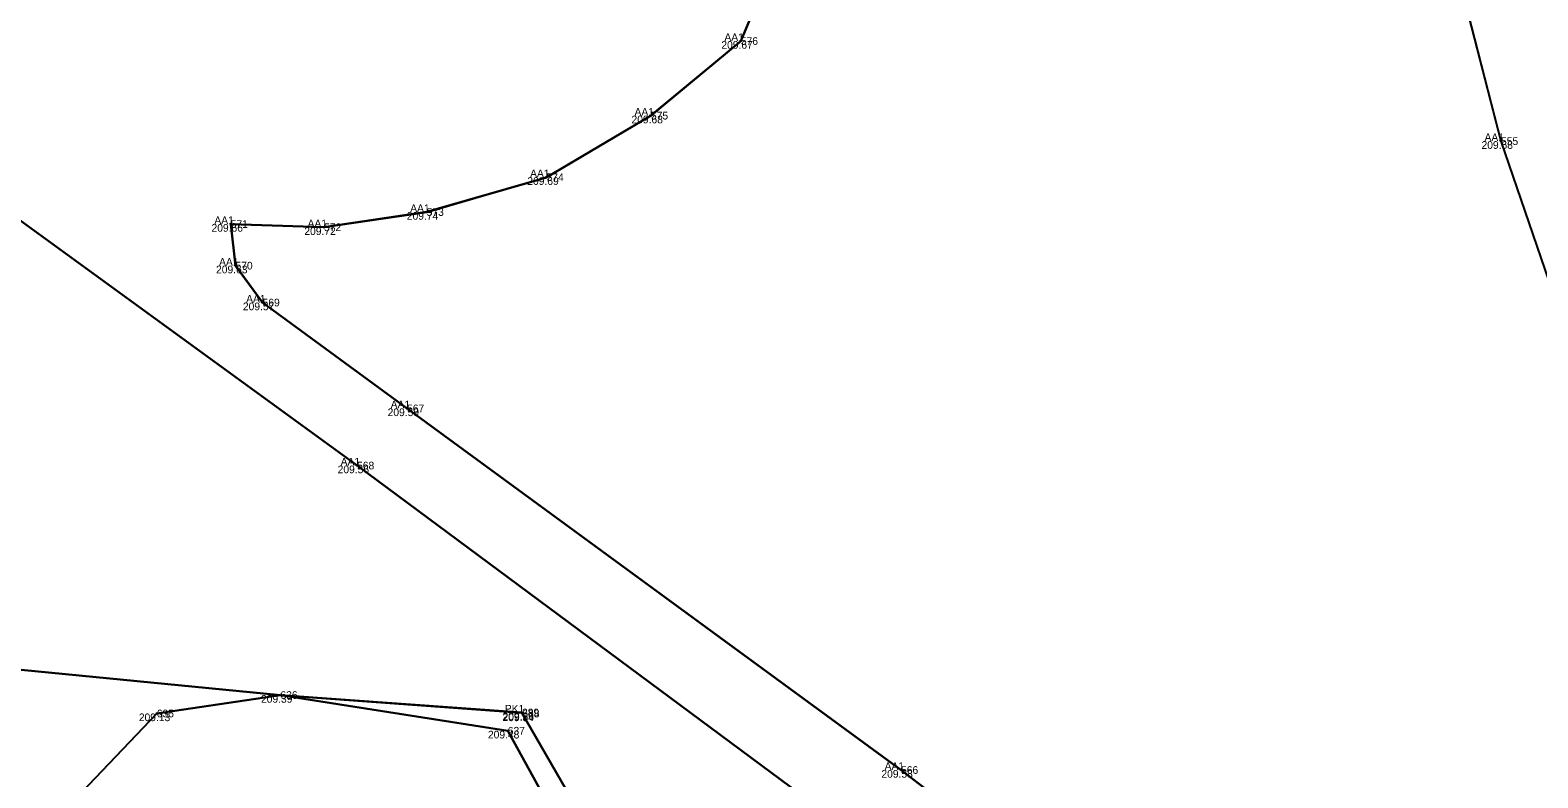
# Model space of a CAD drawing. Extents: x -262982 to -262706, y -1238714 to -1237093.
# Drawn here: x -262950.29 to -262911.03, y -1238413.92 to -1238394.45 of the extents above; entities that cross this region are included whole.
import ezdxf

# ---------------------------------------------------------------- set-up
doc = ezdxf.new("R2010")
doc.units = 0
for name, color, linetype in [('02_Oplotenie', 7, 'Continuous'), ('03_Asfalt', 7, 'Continuous'), ('05_Hrana_terénu', 7, 'Continuous'), ('10', 7, 'Continuous'), ('Groma (21)', 7, 'Continuous'), ('Groma (22)', 7, 'Continuous'), ('Groma (23)', 7, 'Continuous'), ('Groma (24)', 7, 'Continuous'), ('U001_Zeleň_mimo', 7, 'Continuous'), ('U001_Zeleň_vnútro', 7, 'Continuous'), ('U001_Zeleň_zatrávňovač', 7, 'Continuous'), ('U002_Asfalt', 7, 'Continuous'), ('U002_Zeleň_mimo', 7, 'Continuous')]:
    doc.layers.add(name, color=color, linetype=linetype)

msp = doc.modelspace()

# ---------------------------------------------------------------- linework, layer by layer
at = {"layer": '02_Oplotenie'}
msp.add_lwpolyline([(-262935.956, -1238414.87), (-262937.48, -1238412.215), (-262943.77, -1238411.76), (-262954.62, -1238410.7), (-262953.69, -1238416.69), (-262950.95, -1238424.18), (-262948.2, -1238429.713), (-262938.076, -1238450.416), (-262931.824, -1238462.793)], dxfattribs=at)
at = {"layer": '03_Asfalt'}
for points in [[(-262913.444, -1238391.676), (-262911.985, -1238397.337), (-262910.006, -1238403.107), (-262907.769, -1238409.039), (-262901.709, -1238424.56), (-262896.942, -1238436.871), (-262897.547, -1238437.016), (-262898.706, -1238436.381), (-262904.848, -1238431.522), (-262916.36, -1238422.355), (-262927.608, -1238413.712), (-262940.472, -1238404.296), (-262944.235, -1238401.54), (-262944.94, -1238400.579), (-262945.063, -1238399.495), (-262942.635, -1238399.58), (-262939.962, -1238399.183), (-262936.84, -1238398.276), (-262934.121, -1238396.673), (-262931.78, -1238394.73), (-262927.567, -1238384.599)], [(-262842.406, -1238598.306), (-262850.452, -1238578.707), (-262858.82, -1238561.234), (-262870.509, -1238539), (-262873.344, -1238533.53), (-262876.375, -1238529.239), (-262880.031, -1238521.826), (-262869.115, -1238517.45), (-262870.175, -1238508.052), (-262871.319, -1238501.744), (-262886.895, -1238462.375), (-262895.067, -1238441.663), (-262905.824, -1238433.621), (-262917.716, -1238423.993), (-262928.896, -1238415.327), (-262941.774, -1238405.784), (-262954.673, -1238396.412), (-262962.054, -1238391.026)]]:
    msp.add_lwpolyline(points, dxfattribs=at)
at = {"layer": '05_Hrana_terénu'}
msp.add_lwpolyline([(-262927.783, -1238467.254), (-262930.465, -1238462.525), (-262936.779, -1238449.928), (-262947.402, -1238428.273), (-262948.67, -1238426), (-262950.05, -1238420.42), (-262949.48, -1238414.85), (-262946.99, -1238412.24), (-262943.77, -1238411.76), (-262937.85, -1238412.69), (-262935.589, -1238416.796), (-262931.931, -1238424.05), (-262925.295, -1238433.06), (-262918.113, -1238442.283), (-262917.125, -1238443.234)], dxfattribs=at)
at = {"layer": '10'}
msp.add_lwpolyline([(-262982.434, -1238375.977), (-262968.907, -1238386.238), (-262962.054, -1238391.026), (-262954.673, -1238396.412), (-262941.774, -1238405.784), (-262928.896, -1238415.327), (-262917.716, -1238423.993), (-262905.824, -1238433.621), (-262895.067, -1238441.663), (-262870.407, -1238460.6)], dxfattribs=at)
at = {"layer": 'Groma (21)'}
for centre in [(-262931.78, -1238394.73), (-262934.121, -1238396.673), (-262911.985, -1238397.337), (-262936.84, -1238398.276), (-262939.962, -1238399.183), (-262945.063, -1238399.495), (-262942.635, -1238399.58), (-262944.94, -1238400.579), (-262944.235, -1238401.54), (-262940.472, -1238404.296), (-262941.774, -1238405.784), (-262943.77, -1238411.76), (-262946.99, -1238412.24), (-262937.48, -1238412.215), (-262937.47, -1238412.24), (-262937.85, -1238412.69), (-262927.608, -1238413.712)]:
    msp.add_circle(centre, 0.01, dxfattribs=at)
at = {"layer": 'U001_Zeleň_mimo'}
for points in [[(-262962.05, -1238391.03), (-262954.67, -1238396.41), (-262941.77, -1238405.78), (-262928.9, -1238415.33), (-262917.72, -1238423.99), (-262905.82, -1238433.62), (-262895.07, -1238441.66), (-262886.9, -1238462.38), (-262871.32, -1238501.74), (-262870.18, -1238508.05), (-262869.12, -1238517.45), (-262880.03, -1238521.83), (-262876.38, -1238529.24), (-262873.34, -1238533.53), (-262870.51, -1238539), (-262858.82, -1238561.23), (-262850.45, -1238578.71), (-262842.41, -1238598.31)], [(-262962.05, -1238391.03), (-262954.67, -1238396.41), (-262941.77, -1238405.78), (-262928.9, -1238415.33), (-262917.72, -1238423.99), (-262905.82, -1238433.62), (-262895.07, -1238441.66), (-262886.9, -1238462.38), (-262871.32, -1238501.74), (-262870.18, -1238508.05), (-262869.12, -1238517.45), (-262880.03, -1238521.83), (-262876.38, -1238529.24), (-262873.34, -1238533.53), (-262870.51, -1238539), (-262858.82, -1238561.23), (-262850.45, -1238578.71), (-262842.41, -1238598.31)], [(-262911.84, -1238449.79), (-262917.13, -1238443.23), (-262918.11, -1238442.28), (-262925.3, -1238433.06), (-262931.93, -1238424.05), (-262935.59, -1238416.8), (-262935.96, -1238414.87), (-262937.48, -1238412.22), (-262943.77, -1238411.76), (-262954.62, -1238410.7), (-262953.69, -1238416.69), (-262950.95, -1238424.18), (-262948.2, -1238429.71), (-262938.08, -1238450.42)]]:
    msp.add_lwpolyline(points, dxfattribs=at)
at = {"layer": 'U001_Zeleň_vnútro'}
msp.add_lwpolyline([(-262908.34, -1238509.94), (-262919.31, -1238488.27), (-262929.26, -1238468.08), (-262927.92, -1238467.26), (-262930.86, -1238463.25), (-262931.82, -1238462.79), (-262938.08, -1238450.42), (-262948.2, -1238429.71), (-262950.95, -1238424.18), (-262953.69, -1238416.69), (-262954.62, -1238410.7), (-262943.77, -1238411.76), (-262946.99, -1238412.24), (-262949.48, -1238414.85), (-262950.05, -1238420.42), (-262948.67, -1238426), (-262947.4, -1238428.27), (-262936.78, -1238449.93), (-262930.47, -1238462.53), (-262927.78, -1238467.25), (-262927.47, -1238468.81), (-262918.2, -1238487.16), (-262908.25, -1238507.59)], dxfattribs=at)
msp.add_lwpolyline([(-262935.59, -1238416.8), (-262937.85, -1238412.69), (-262943.77, -1238411.76), (-262937.48, -1238412.22), (-262935.96, -1238414.87)], close=True, dxfattribs=at)
at = {"layer": 'U001_Zeleň_zatrávňovač'}
msp.add_lwpolyline([(-262949.48, -1238414.85), (-262946.99, -1238412.24), (-262943.77, -1238411.76), (-262937.85, -1238412.69), (-262935.59, -1238416.8)], dxfattribs=at)
at = {"layer": 'U002_Asfalt'}
msp.add_lwpolyline([(-262927.57, -1238384.6), (-262931.78, -1238394.73), (-262934.12, -1238396.67), (-262936.84, -1238398.28), (-262939.96, -1238399.18), (-262942.64, -1238399.58), (-262945.06, -1238399.5), (-262944.94, -1238400.58), (-262944.24, -1238401.54), (-262940.47, -1238404.3), (-262927.61, -1238413.71), (-262916.36, -1238422.36), (-262904.85, -1238431.52), (-262898.71, -1238436.38), (-262897.55, -1238437.02), (-262896.94, -1238436.87), (-262895.07, -1238441.66), (-262905.82, -1238433.62), (-262917.72, -1238423.99), (-262928.9, -1238415.33), (-262941.77, -1238405.78), (-262954.67, -1238396.41), (-262962.05, -1238391.03)], dxfattribs=at)
at = {"layer": 'U002_Zeleň_mimo'}
msp.add_lwpolyline([(-262913.44, -1238391.68), (-262911.99, -1238397.34), (-262910.01, -1238403.11), (-262907.77, -1238409.04), (-262901.71, -1238424.56), (-262896.94, -1238436.87), (-262897.55, -1238437.02), (-262898.71, -1238436.38), (-262904.85, -1238431.52), (-262916.36, -1238422.36), (-262927.61, -1238413.71), (-262940.47, -1238404.3), (-262944.24, -1238401.54), (-262944.94, -1238400.58), (-262945.06, -1238399.5), (-262942.64, -1238399.58), (-262939.96, -1238399.18), (-262936.84, -1238398.28), (-262934.12, -1238396.67), (-262931.78, -1238394.73), (-262927.57, -1238384.6)], dxfattribs=at)

# ---------------------------------------------------------------- texts
at = {"layer": 'Groma (22)'}
for s, p in [('576', (-262931.78, -1238394.83)), ('575', (-262934.121, -1238396.773)), ('555', (-262911.985, -1238397.437)), ('574', (-262936.84, -1238398.376)), ('573', (-262939.962, -1238399.283)), ('571', (-262945.063, -1238399.595)), ('572', (-262942.635, -1238399.68)), ('570', (-262944.94, -1238400.679)), ('569', (-262944.235, -1238401.64)), ('567', (-262940.472, -1238404.396)), ('568', (-262941.774, -1238405.884)), ('636', (-262943.77, -1238411.86)), ('635', (-262946.99, -1238412.34)), ('289', (-262937.48, -1238412.315)), ('638', (-262937.47, -1238412.34)), ('637', (-262937.85, -1238412.79)), ('566', (-262927.608, -1238413.812))]:
    msp.add_text(s, height=0.2, dxfattribs=at).set_placement(p)
at = {"layer": 'Groma (23)'}
for s, p in [('209.67', (-262932.288, -1238394.93)), ('209.68', (-262934.628, -1238396.873)), ('209.68', (-262912.492, -1238397.537)), ('209.69', (-262937.342, -1238398.476)), ('209.74', (-262940.479, -1238399.383)), ('209.66', (-262945.565, -1238399.695)), ('209.72', (-262943.148, -1238399.78)), ('209.63', (-262945.447, -1238400.779)), ('209.57', (-262944.748, -1238401.74)), ('209.59', (-262940.979, -1238404.496)), ('209.56', (-262942.281, -1238405.984)), ('209.39', (-262944.277, -1238411.96)), ('209.13', (-262947.458, -1238412.44)), ('209.56', (-262937.987, -1238412.415)), ('209.54', (-262937.987, -1238412.44)), ('209.48', (-262938.367, -1238412.89)), ('209.58', (-262928.12, -1238413.912))]:
    msp.add_text(s, height=0.2, dxfattribs=at).set_placement(p)
at = {"layer": 'Groma (24)'}
for s, p in [('AA1', (-262932.208, -1238394.73)), ('AA1', (-262934.549, -1238396.673)), ('AA1', (-262912.413, -1238397.337)), ('AA1', (-262937.268, -1238398.276)), ('AA1', (-262940.39, -1238399.183)), ('AA1', (-262945.491, -1238399.495)), ('AA1', (-262943.063, -1238399.58)), ('AA1', (-262945.368, -1238400.579)), ('AA1', (-262944.663, -1238401.54)), ('AA1', (-262940.9, -1238404.296)), ('AA1', (-262942.202, -1238405.784)), ('PK1', (-262937.927, -1238412.215)), ('AA1', (-262928.036, -1238413.712))]:
    msp.add_text(s, height=0.2, dxfattribs=at).set_placement(p)

doc.saveas('drawing.dxf')
